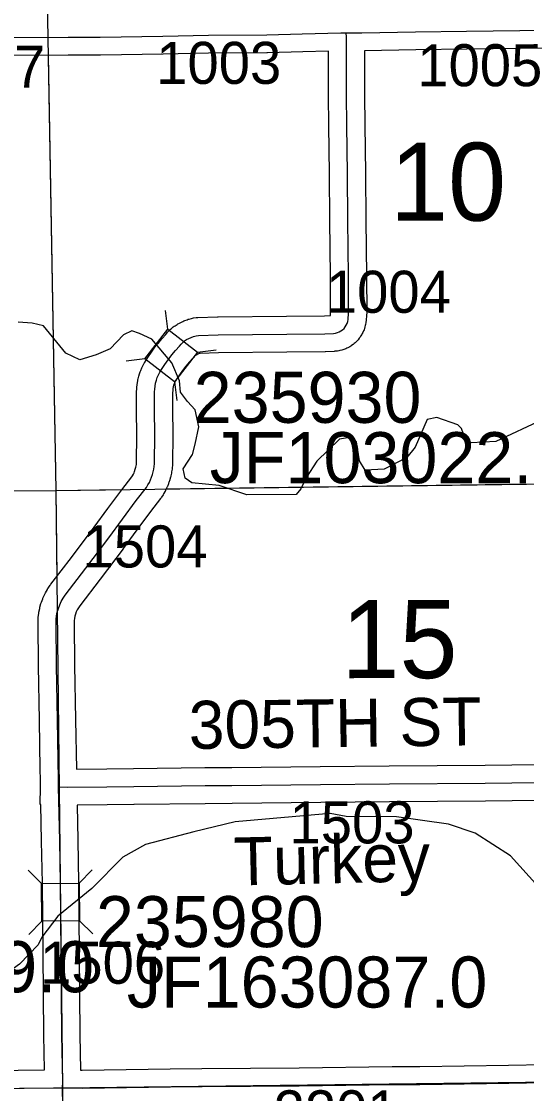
# Model space of a CAD drawing. Extents: x 23.6 to 68.7, y -63 to -29.
# Drawn here: x 35.747 to 36.588, y -54.733 to -52.947 of the extents above; entities that cross this region are included whole.
import ezdxf

# ---------------------------------------------------------------- set-up
doc = ezdxf.new("R2010")
doc.units = 0
for name, color, linetype in [('tdCoHydroRiver', 7, 'Continuous'), ('tdCoHydroTxtLg', 7, 'Continuous'), ('tdCoSecRdNmbr', 7, 'Continuous'), ('tdCoSecRdTxt', 7, 'Continuous'), ('tdCoSecRteBand', 7, 'Continuous'), ('tdCoSecRteCL', 7, 'Continuous'), ('tdCoSectLine', 7, 'Continuous'), ('tdCoSectLinePart', 7, 'Continuous'), ('tdCoSectNmbr', 7, 'Continuous'), ('tdCoStrucSec', 7, 'Continuous'), ('tdCoStrucSecCoName', 7, 'Continuous'), ('tdCoStrucSecFHWANum', 7, 'Continuous'), ('tdCoSurfAsphalt', 7, 'Continuous'), ('tdCoSurfGravel', 7, 'Continuous')]:
    doc.layers.add(name, color=color, linetype=linetype)

msp = doc.modelspace()

# ---------------------------------------------------------------- linework, layer by layer
at = {"layer": 'tdCoHydroRiver'}
for points in [[(36.032, -53.6686), (36.0366, -53.6512), (36.0427, -53.6228), (36.0362, -53.5944), (36.0234, -53.5803), (36.0122, -53.5646), (36.0105, -53.5457), (35.9976, -53.5158), (35.9642, -53.4766), (35.9436, -53.4673), (35.9309, -53.4626), (35.9168, -53.4691), (35.8949, -53.4929), (35.8713, -53.5026), (35.8445, -53.5107), (35.8207, -53.4998), (35.784, -53.4544), (35.7651, -53.4498), (35.7414, -53.4484)], [(36.6156, -53.6103), (36.537, -53.6472), (36.496, -53.6491), (36.4832, -53.635), (36.48, -53.6255), (36.4736, -53.6193), (36.4388, -53.6069), (36.423, -53.6102), (36.4029, -53.6562), (36.3888, -53.6736), (36.3511, -53.6929), (36.3195, -53.6947), (36.3099, -53.679), (36.3049, -53.6475), (36.297, -53.6396), (36.2765, -53.643), (36.2389, -53.6796), (36.2218, -53.7066), (36.2124, -53.7256), (36.2046, -53.7351), (36.1225, -53.7358), (36.0766, -53.7204), (36.0308, -53.716), (36.0197, -53.7082), (36.0164, -53.6924), (36.032, -53.6686)], [(36.5615, -54.3368), (36.5028, -54.2994), (36.4584, -54.284), (36.3715, -54.2721), (36.2878, -54.2712), (36.261, -54.2666), (36.1032, -54.2805), (36.0339, -54.2969), (35.9536, -54.318), (35.9159, -54.3389), (35.8642, -54.3914), (35.8077, -54.4376), (35.7812, -54.4726), (35.775, -54.4852), (35.7436, -54.5171), (35.5867, -54.6304), (35.5491, -54.6623), (35.4974, -54.7179), (35.4881, -54.7385)], [(36.6236, -54.4058), (36.5615, -54.3368)]]:
    msp.add_lwpolyline(points, dxfattribs=at)
at = {"layer": 'tdCoSecRteBand'}
for points in [[(35.6534, -54.6949), (35.7853, -54.6935), (35.7843, -54.6358), (35.7843, -54.6356), (35.7843, -54.6355), (35.7831, -54.4992), (35.7831, -54.4992), (35.7831, -54.4992), (35.7821, -54.3825), (35.7807, -54.3123), (35.7807, -54.3123), (35.7807, -54.3123), (35.7795, -54.2513), (35.7782, -54.2513), (35.779, -54.222), (35.7788, -54.2103), (35.7788, -54.2102), (35.7788, -54.2102), (35.7784, -54.1927), (35.7785, -54.1927), (35.7772, -54.1114), (35.7754, -54.0207), (35.7754, -54.0205), (35.7754, -54.0204), (35.7748, -53.9491), (35.7748, -53.949), (35.7748, -53.9489), (35.7748, -53.9434), (35.7748, -53.9415), (35.775, -53.9397), (35.7758, -53.9335), (35.7759, -53.9324), (35.7761, -53.9312), (35.7774, -53.9251), (35.7776, -53.924), (35.7779, -53.9229), (35.7796, -53.9169), (35.78, -53.9157), (35.7804, -53.9146), (35.7825, -53.9088), (35.7829, -53.9077), (35.7834, -53.9066), (35.786, -53.901), (35.7865, -53.8999), (35.7871, -53.8989), (35.7902, -53.8934), (35.7907, -53.8924), (35.7914, -53.8914), (35.7949, -53.8863), (35.7954, -53.8854), (35.796, -53.8847), (35.8302, -53.84), (35.8683, -53.7895), (35.8909, -53.7587), (35.891, -53.7586), (35.891, -53.7585), (35.9141, -53.7276), (35.9142, -53.7274), (35.9144, -53.7272), (35.9307, -53.706), (35.9321, -53.7039), (35.9334, -53.7015), (35.9345, -53.6992), (35.9354, -53.6967), (35.9365, -53.6932), (35.9375, -53.6899), (35.938, -53.6875), (35.9384, -53.6851), (35.9386, -53.6825), (35.9393, -53.6351), (35.9384, -53.5958), (35.9384, -53.5953), (35.9384, -53.5947), (35.9388, -53.5636), (35.9388, -53.5623), (35.939, -53.5611), (35.9393, -53.557), (35.9398, -53.5521), (35.9399, -53.551), (35.9401, -53.5499), (35.9409, -53.5449), (35.9411, -53.5438), (35.9414, -53.5427), (35.9426, -53.5379), (35.9429, -53.5367), (35.9432, -53.5357), (35.9448, -53.5309), (35.9452, -53.5298), (35.9456, -53.5288), (35.9475, -53.5242), (35.948, -53.5231), (35.9485, -53.5221), (35.9508, -53.5177), (35.9513, -53.5166), (35.9519, -53.5157), (35.9545, -53.5114), (35.9548, -53.5109), (35.9551, -53.5105), (35.9606, -53.5022), (35.9609, -53.5017), (35.9612, -53.5013), (35.967, -53.4932), (35.9673, -53.4928), (35.9677, -53.4923), (35.9737, -53.4845), (35.9741, -53.4841), (35.9745, -53.4837), (35.9808, -53.4761), (35.9812, -53.4756), (35.9816, -53.4752), (35.9875, -53.4687), (35.9892, -53.4664), (35.9903, -53.465), (35.9915, -53.4638), (35.9943, -53.461), (35.9955, -53.4597), (35.9969, -53.4586), (36, -53.4561), (36.0013, -53.455), (36.0028, -53.4541), (36.0062, -53.452), (36.0076, -53.451), (36.0092, -53.4503), (36.0125, -53.4487), (36.0159, -53.4469), (36.0174, -53.4462), (36.019, -53.4456), (36.023, -53.4441), (36.0246, -53.4435), (36.0262, -53.443), (36.0303, -53.442), (36.032, -53.4416), (36.0336, -53.4413), (36.0379, -53.4407), (36.0394, -53.4405), (36.0409, -53.4405), (36.0737, -53.4393), (36.0741, -53.4393), (36.0745, -53.4393), (36.1885, -53.4383), (36.2515, -53.4375), (36.2615, -53.4371), (36.262, -53.4316), (36.2618, -53.3716), (36.2608, -53.2788), (36.2608, -53.2788), (36.2608, -53.2788), (36.26, -53.2013), (36.26, -53.2013), (36.26, -53.2012), (36.2592, -53.1205), (36.2584, -53.071), (36.2584, -53.0708), (36.2584, -53.0706), (36.2582, -53.0028), (36.2582, -53.0026), (36.2582, -53.0025), (36.2583, -52.9969), (36.2155, -52.9979), (36.1566, -52.9998), (36.1562, -52.9998), (36.1559, -52.9998), (36.0588, -53.0004), (35.983, -53.0018), (35.8789, -53.0038), (35.8785, -53.0038), (35.8781, -53.0038), (35.825, -53.0034), (35.6992, -53.0042)], [(36.6912, -52.9911), (36.5772, -52.9923), (36.4887, -52.9935), (36.4887, -52.9935), (36.4886, -52.9935), (36.4036, -52.9945), (36.3183, -52.9963), (36.3182, -53.0027), (36.3184, -53.0703), (36.3192, -53.1196), (36.3192, -53.1197), (36.3192, -53.1198), (36.32, -53.2007), (36.3208, -53.2782), (36.3218, -53.3711), (36.3218, -53.3712), (36.3218, -53.3713), (36.322, -53.4329), (36.322, -53.4343), (36.3219, -53.4357), (36.3209, -53.4465), (36.3208, -53.4476), (36.3206, -53.4488), (36.32, -53.452), (36.3197, -53.4539), (36.3192, -53.4558), (36.3182, -53.459), (36.3176, -53.4608), (36.3168, -53.4626), (36.3155, -53.4656), (36.3147, -53.4674), (36.3137, -53.469), (36.3119, -53.4718), (36.3109, -53.4735), (36.3097, -53.475), (36.3076, -53.4776), (36.3064, -53.4791), (36.305, -53.4804), (36.3026, -53.4827), (36.3012, -53.484), (36.2996, -53.4852), (36.2969, -53.4871), (36.2954, -53.4883), (36.2937, -53.4892), (36.2908, -53.4908), (36.2891, -53.4917), (36.2873, -53.4924), (36.2842, -53.4936), (36.2824, -53.4943), (36.2805, -53.4948), (36.2773, -53.4956), (36.2754, -53.4961), (36.2735, -53.4963), (36.2702, -53.4967), (36.2691, -53.4968), (36.268, -53.4969), (36.2536, -53.4975), (36.2531, -53.4975), (36.2527, -53.4975), (36.1892, -53.4983), (36.1891, -53.4983), (36.1891, -53.4983), (36.0754, -53.4993), (36.0446, -53.5004), (36.0436, -53.5005), (36.0427, -53.5007), (36.0419, -53.5011), (36.0396, -53.5022), (36.0392, -53.5024), (36.0389, -53.5026), (36.0368, -53.5036), (36.0363, -53.5039), (36.0359, -53.5042), (36.0355, -53.5046), (36.0341, -53.5064), (36.0334, -53.5073), (36.0327, -53.5081), (36.0264, -53.5151), (36.0208, -53.5218), (36.0154, -53.5287), (36.0102, -53.5359), (36.0054, -53.5432), (36.0037, -53.546), (36.0024, -53.5484), (36.0014, -53.5509), (36.0005, -53.5534), (35.9999, -53.5561), (35.9994, -53.5587), (35.9991, -53.5625), (35.9991, -53.5626), (35.9991, -53.5627), (35.9988, -53.5656), (35.9984, -53.595), (35.9993, -53.6343), (35.9993, -53.6349), (35.9993, -53.6355), (35.9985, -53.6844), (35.9985, -53.6853), (35.9985, -53.6862), (35.9981, -53.6908), (35.998, -53.6919), (35.9979, -53.6929), (35.9972, -53.6975), (35.997, -53.6985), (35.9968, -53.6996), (35.9958, -53.7041), (35.9956, -53.7051), (35.9952, -53.7061), (35.9939, -53.7105), (35.9939, -53.7106), (35.9939, -53.7106), (35.9925, -53.7152), (35.9922, -53.7162), (35.9918, -53.7172), (35.9901, -53.7217), (35.9897, -53.7227), (35.9893, -53.7236), (35.9872, -53.7279), (35.9868, -53.7289), (35.9863, -53.7298), (35.9839, -53.734), (35.9834, -53.7349), (35.9828, -53.7358), (35.9802, -53.7398), (35.9796, -53.7408), (35.9789, -53.7417), (35.9621, -53.7636), (35.9392, -53.7943), (35.9166, -53.8252), (35.9165, -53.8253), (35.9163, -53.8255), (35.8781, -53.8762), (35.878, -53.8763), (35.8779, -53.8764), (35.8442, -53.9204), (35.8419, -53.9238), (35.84, -53.9272), (35.8384, -53.9307), (35.837, -53.9344), (35.836, -53.9381), (35.8352, -53.942), (35.8348, -53.9452), (35.8348, -53.9488), (35.8354, -54.0197), (35.8372, -54.1103), (35.8372, -54.1103), (35.8372, -54.1104), (35.8385, -54.1924)], [(35.8385, -54.1924), (35.8892, -54.1919), (35.8892, -54.1919), (35.8892, -54.1919), (35.9339, -54.1916), (36.0524, -54.1901), (36.0525, -54.1901), (36.0525, -54.1901), (36.0973, -54.1897), (36.2448, -54.1883), (36.3594, -54.1869), (36.3595, -54.1869), (36.3596, -54.1869), (36.5193, -54.1857), (36.6526, -54.1843)], [(36.6531, -54.2443), (36.5199, -54.2457), (36.5199, -54.2457), (36.5198, -54.2457), (36.3601, -54.2469), (36.2455, -54.2483), (36.2455, -54.2483), (36.2454, -54.2483), (36.0979, -54.2497), (36.0979, -54.2497), (36.0979, -54.2497), (36.0531, -54.2501), (35.9346, -54.2516), (35.9345, -54.2516), (35.9344, -54.2516), (35.8897, -54.2519), (35.8396, -54.2524), (35.8407, -54.3111), (35.8421, -54.3815), (35.8421, -54.3817), (35.8421, -54.3819), (35.8431, -54.4987), (35.8443, -54.6348), (35.8453, -54.6937), (35.8458, -54.6937), (35.8458, -54.6937), (35.8484, -54.6937)], [(35.8484, -54.6937), (35.9949, -54.6918), (35.9949, -54.6918), (35.9949, -54.6918), (36.0476, -54.6912), (36.0476, -54.6912), (36.0477, -54.6912), (36.2094, -54.6898), (36.3644, -54.6878), (36.3645, -54.6878), (36.3646, -54.6878), (36.4104, -54.6876), (36.5582, -54.6853), (36.7365, -54.6821)]]:
    msp.add_lwpolyline(points, dxfattribs=at)
at = {"layer": 'tdCoSecRteCL'}
for points in [[(35.563, -52.9746), (35.6287, -52.9748), (35.699, -52.9742), (35.825, -52.9734), (35.8783, -52.9738), (35.9825, -52.9718), (36.0584, -52.9704), (36.1557, -52.9698), (36.2146, -52.968), (36.2792, -52.9664), (36.2878, -52.9664)], [(35.809, -54.2221), (35.8087, -54.2097), (35.8072, -54.1109), (35.8054, -54.0201), (35.8048, -53.9489), (35.8048, -53.9434), (35.8056, -53.9372), (35.8068, -53.9311), (35.8085, -53.9251), (35.8107, -53.9192), (35.8133, -53.9135), (35.8163, -53.9081), (35.8198, -53.9029), (35.8541, -53.8581), (35.8924, -53.8074), (35.9151, -53.7765), (35.9382, -53.7455), (35.9551, -53.7234), (35.9577, -53.7194), (35.9601, -53.7152), (35.9621, -53.7109), (35.9638, -53.7065), (35.9652, -53.7019), (35.9665, -53.6975), (35.9675, -53.693), (35.9682, -53.6885), (35.9685, -53.6839), (35.9693, -53.635), (35.9684, -53.5951), (35.9688, -53.564), (35.9692, -53.5598), (35.9697, -53.5548), (35.9705, -53.5499), (35.9717, -53.5451), (35.9733, -53.5404), (35.9752, -53.5358), (35.9775, -53.5313), (35.9801, -53.5271), (35.9856, -53.5188), (35.9913, -53.5108), (35.9974, -53.5029), (36.0038, -53.4953), (36.0105, -53.488), (36.0129, -53.4848), (36.0157, -53.482), (36.0188, -53.4795), (36.0222, -53.4773), (36.0258, -53.4756), (36.0296, -53.4736), (36.0336, -53.4721), (36.0378, -53.471), (36.042, -53.4704), (36.0748, -53.4693), (36.1888, -53.4683), (36.2523, -53.4675), (36.2667, -53.4669), (36.27, -53.4665), (36.2732, -53.4657), (36.2763, -53.4645), (36.2792, -53.4629), (36.2819, -53.4609), (36.2843, -53.4587), (36.2864, -53.4561), (36.2881, -53.4533), (36.2895, -53.4502), (36.2904, -53.4471), (36.291, -53.4438), (36.292, -53.433), (36.2918, -53.3714), (36.2908, -53.2785), (36.29, -53.201), (36.2892, -53.1201), (36.2884, -53.0705), (36.2882, -53.0027), (36.2884, -52.9735), (36.2878, -52.9664)], [(36.2878, -52.9664), (36.3139, -52.9664), (36.4031, -52.9645), (36.4883, -52.9635), (36.5769, -52.9623), (36.6909, -52.9611), (36.7254, -52.9608), (36.7826, -52.9598), (36.7865, -52.9597)], [(35.809, -54.2221), (35.8233, -54.2225), (35.8894, -54.2219), (35.9342, -54.2216), (36.0528, -54.2201), (36.0976, -54.2197), (36.2452, -54.2183), (36.3598, -54.2169), (36.5196, -54.2157), (36.653, -54.2143)], [(35.8156, -54.7235), (35.8157, -54.7132), (35.8143, -54.6352), (35.8131, -54.4989), (35.8121, -54.3821), (35.8107, -54.3117), (35.809, -54.2221)], [(35.8156, -54.7235), (35.8485, -54.7237), (35.9953, -54.7218), (36.0479, -54.7212), (36.2097, -54.7198), (36.3648, -54.7178), (36.4107, -54.7176), (36.5587, -54.7153), (36.7371, -54.7121), (36.8031, -54.7115), (36.8134, -54.7113)], [(34.299, -54.7347), (34.3311, -54.7343), (34.3862, -54.734), (34.4912, -54.7332), (34.558, -54.7328), (34.692, -54.732), (34.7476, -54.732), (34.8948, -54.7297), (34.9372, -54.7289), (35.0976, -54.7291), (35.2363, -54.7279), (35.2866, -54.7283), (35.4622, -54.7269), (35.6538, -54.7249), (35.8005, -54.7233), (35.8156, -54.7235)], [(35.8155, -54.738), (35.8156, -54.7235)]]:
    msp.add_lwpolyline(points, dxfattribs=at)
at = {"layer": 'tdCoSectLine'}
for points in [[(35.7866, -52.7238), (35.8042, -53.7285)], [(35.8042, -53.7285), (36.7946, -53.7151)], [(34.7885, -53.7294), (35.8042, -53.7285)], [(35.8042, -53.7285), (35.8152, -54.7235)], [(35.8152, -54.7235), (36.8131, -54.7113)], [(34.8144, -54.7309), (35.8152, -54.7235)], [(35.8152, -54.7235), (35.8256, -55.7233)]]:
    msp.add_lwpolyline(points, dxfattribs=at)
at = {"layer": 'tdCoSectLinePart'}
for points in [[(35.7915, -53.004), (35.8042, -53.7285)], [(35.9876, -53.726), (36.7647, -53.7155)], [(34.7885, -53.7294), (35.8042, -53.7285)], [(35.8042, -53.7285), (35.9139, -53.727)], [(35.8042, -53.7285), (35.8058, -53.8712)]]:
    msp.add_lwpolyline(points, dxfattribs=at)
at = {"layer": 'tdCoStrucSec'}
for p, q in [((35.991, -53.4598), (35.9871, -53.4288)), ((36.0404, -53.4983), (36.0714, -53.4944)), ((35.9525, -53.5092), (35.9215, -53.5131)), ((36.0019, -53.5477), (36.0058, -53.5787)), ((35.7805, -54.3831), (35.7582, -54.3611)), ((35.8431, -54.3825), (35.865, -54.3602)), ((35.781, -54.4457), (35.7591, -54.468)), ((35.8436, -54.4451), (35.8659, -54.4671))]:
    msp.add_line(p, q, dxfattribs=at)
for points in [[(35.9525, -53.5092), (35.991, -53.4598), (36.0404, -53.4983), (36.0019, -53.5477)], [(35.781, -54.4457), (35.7805, -54.3831), (35.8431, -54.3825), (35.8436, -54.4451)]]:
    msp.add_lwpolyline(points, close=True, dxfattribs=at)
at = {"layer": 'tdCoSurfAsphalt'}
msp.add_lwpolyline([(34.4912, -54.7332), (34.558, -54.7328), (34.692, -54.732), (34.7476, -54.732), (34.8948, -54.7297), (34.9372, -54.7289), (35.0976, -54.7291), (35.2363, -54.7279), (35.2866, -54.7283), (35.4622, -54.7269), (35.6538, -54.7249), (35.8005, -54.7233), (35.8156, -54.7235), (35.8485, -54.7237), (35.9953, -54.7218), (36.0479, -54.7212), (36.2097, -54.7198), (36.3648, -54.7178), (36.4107, -54.7176), (36.5587, -54.7153), (36.7371, -54.7121)], dxfattribs=at)
at = {"layer": 'tdCoSurfGravel'}
for points in [[(36.2878, -52.9664), (36.3139, -52.9664), (36.4031, -52.9645), (36.4883, -52.9635), (36.5769, -52.9623), (36.6909, -52.9611), (36.7254, -52.9608), (36.7826, -52.9598), (36.7865, -52.9597), (36.8163, -52.9586), (36.8893, -52.958), (36.9886, -52.9576), (37.0393, -52.9566), (37.1904, -52.955), (37.25, -52.9548), (37.2559, -52.9544), (37.2596, -52.9545), (37.2632, -52.9541), (37.2667, -52.9532), (37.27, -52.9519), (37.2732, -52.9502)], [(35.563, -52.9746), (35.6287, -52.9748), (35.699, -52.9742), (35.825, -52.9734), (35.8783, -52.9738), (35.9825, -52.9718), (36.0584, -52.9704), (36.1557, -52.9698), (36.2146, -52.968), (36.2792, -52.9664), (36.2878, -52.9664)], [(35.8156, -54.7235), (35.8157, -54.7132), (35.8143, -54.6352), (35.8131, -54.4989), (35.8121, -54.3821), (35.8107, -54.3117), (35.809, -54.2221), (35.8087, -54.2097), (35.8072, -54.1109), (35.8054, -54.0201), (35.8048, -53.9489), (35.8048, -53.9434), (35.8056, -53.9372), (35.8068, -53.9311), (35.8085, -53.9251), (35.8107, -53.9192), (35.8133, -53.9135), (35.8163, -53.9081), (35.8198, -53.9029), (35.8541, -53.8581), (35.8924, -53.8074), (35.9151, -53.7765), (35.9382, -53.7455), (35.9551, -53.7234), (35.9577, -53.7194), (35.9601, -53.7152), (35.9621, -53.7109), (35.9638, -53.7065), (35.9652, -53.7019), (35.9665, -53.6975), (35.9675, -53.693), (35.9682, -53.6885), (35.9685, -53.6839), (35.9693, -53.635), (35.9684, -53.5951), (35.9688, -53.564), (35.9692, -53.5598), (35.9697, -53.5548), (35.9705, -53.5499), (35.9717, -53.5451), (35.9733, -53.5404), (35.9752, -53.5358), (35.9775, -53.5313), (35.9801, -53.5271), (35.9856, -53.5188), (35.9913, -53.5108), (35.9974, -53.5029), (36.0038, -53.4953), (36.0105, -53.488), (36.0129, -53.4848), (36.0157, -53.482), (36.0188, -53.4795), (36.0222, -53.4773), (36.0258, -53.4756), (36.0296, -53.4736), (36.0336, -53.4721), (36.0378, -53.471), (36.042, -53.4704), (36.0748, -53.4693), (36.1888, -53.4683), (36.2523, -53.4675), (36.2667, -53.4669), (36.27, -53.4665), (36.2732, -53.4657), (36.2763, -53.4645), (36.2792, -53.4629), (36.2819, -53.4609), (36.2843, -53.4587), (36.2864, -53.4561), (36.2881, -53.4533), (36.2895, -53.4502), (36.2904, -53.4471), (36.291, -53.4438), (36.292, -53.433), (36.2918, -53.3714), (36.2908, -53.2785), (36.29, -53.201), (36.2892, -53.1201), (36.2884, -53.0705), (36.2882, -53.0027), (36.2884, -52.9735), (36.2878, -52.9664)], [(35.809, -54.2221), (35.8233, -54.2225), (35.8894, -54.2219), (35.9342, -54.2216), (36.0528, -54.2201), (36.0976, -54.2197), (36.2452, -54.2183), (36.3598, -54.2169), (36.5196, -54.2157), (36.653, -54.2143), (36.7092, -54.2143), (36.7899, -54.213), (36.7925, -54.2131), (36.7951, -54.2128), (36.7976, -54.2121), (36.8, -54.211), (36.8022, -54.2095), (36.8041, -54.2077), (36.8057, -54.2056), (36.8069, -54.2033)], [(35.8155, -54.738), (35.8156, -54.7235)]]:
    msp.add_lwpolyline(points, dxfattribs=at)

# ---------------------------------------------------------------- texts
at = {"layer": 'tdCoHydroTxtLg'}
msp.add_text('Turkey', height=0.08, rotation=1.3231, dxfattribs=at).set_placement((36.1016, -54.3865))
at = {"layer": 'tdCoSecRdNmbr'}
for s, rotation, p in [('0907', 0.028, (35.5786, -53.0578)), ('1003', 0.0283, (35.9715, -53.0515)), ('1005', 0.0287, (36.4063, -53.0554)), ('1004', 0.0285, (36.254, -53.4327)), ('1504', 0.0282, (35.8487, -53.8568)), ('1503', 0.0285, (36.1935, -54.3163)), ('1506', 0.0282, (35.7781, -54.55)), ('2201', 0.0285, (36.167, -54.7975))]:
    msp.add_text(s, height=0.07, rotation=rotation, dxfattribs=at).set_placement(p)
at = {"layer": 'tdCoSecRdTxt'}
msp.add_text('305TH ST', height=0.08, rotation=0.7415, dxfattribs=at).set_placement((36.0261, -54.1591))
at = {"layer": 'tdCoSectNmbr'}
for s, rotation, p in [('10', 0.0286, (36.3609, -53.2794)), ('15', 0.0285, (36.28, -54.0411))]:
    msp.add_text(s, height=0.13, rotation=rotation, dxfattribs=at).set_placement(p)
at = {"layer": 'tdCoStrucSecCoName'}
for s, p in [('JF103022.0', (36.0606, -53.7164)), ('JF213129.0', (35.2677, -54.5641)), ('JF163087.0', (35.9226, -54.5896))]:
    msp.add_text(s, height=0.085, dxfattribs=at).set_placement(p)
at = {"layer": 'tdCoStrucSecFHWANum'}
for s, p in [('235930', (36.0339, -53.6159)), ('235980', (35.8711, -54.489))]:
    msp.add_text(s, height=0.085, dxfattribs=at).set_placement(p)

doc.saveas('drawing.dxf')
